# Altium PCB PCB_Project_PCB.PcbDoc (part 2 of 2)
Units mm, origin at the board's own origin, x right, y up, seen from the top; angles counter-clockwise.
Board outline 177.8 x 50.8 mm, 4 copper layers (Top Layer, Signal Layer 1, Signal Layer 2, Bottom Layer), stack 1.016 mm thick; 119 components, 90 nets, 392 pads, 439 vias.
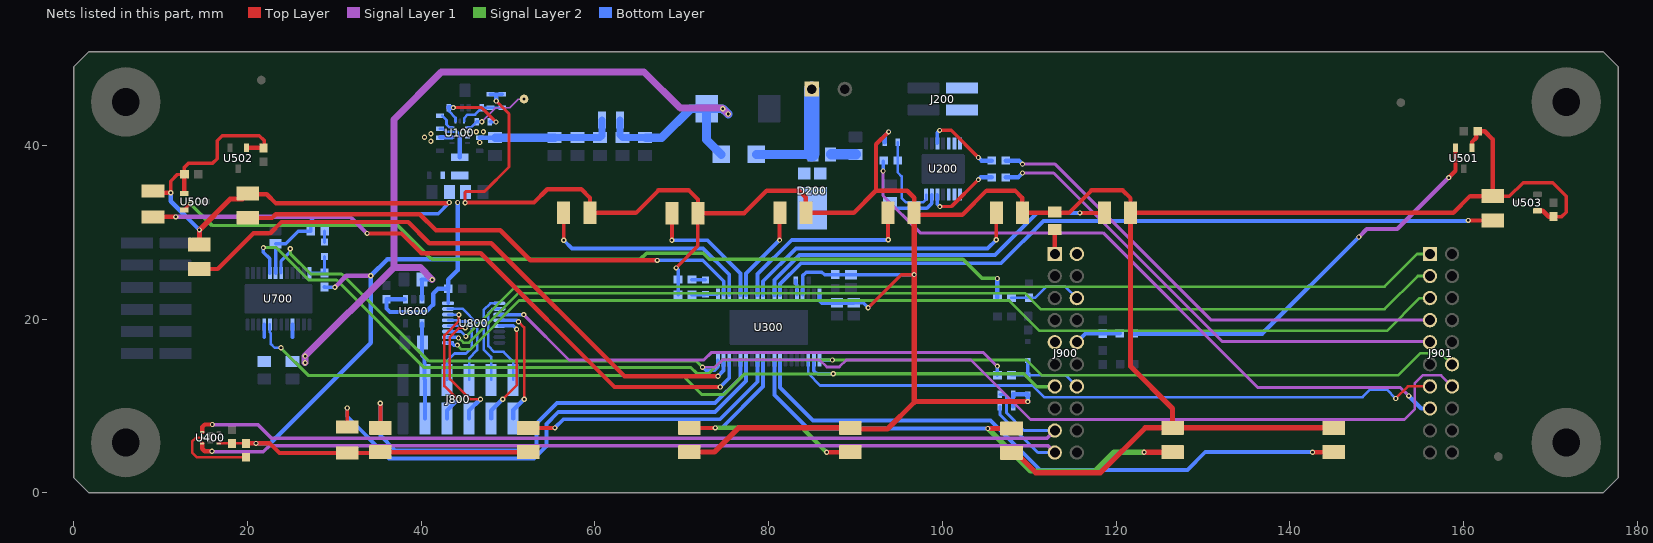
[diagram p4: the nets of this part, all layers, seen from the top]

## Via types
v1: diameter 0.6, hole 0.3, Top Layer to Bottom Layer, 386 vias
v2: diameter 0.5, hole 0.2, Top Layer to Bottom Layer, tented both sides, 30 vias
v3: diameter 0.5, hole 0.2, Top Layer to Bottom Layer, 23 vias

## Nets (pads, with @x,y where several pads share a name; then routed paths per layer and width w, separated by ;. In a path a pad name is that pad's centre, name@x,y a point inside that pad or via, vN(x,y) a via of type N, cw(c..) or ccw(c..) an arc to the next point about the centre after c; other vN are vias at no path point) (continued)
HS_DIAG: J901.9 R201.2 | length 57
  Signal Layer 1 w0.35: v1(109.22,36.83) 112.801,36.83 132.182,17.45 J901.9@156.058,17.45
  Bottom Layer w0.5: R201.2@107.277,36.322 108.712,36.322 v1(109.22,36.83)
HS_DIAG_STAT: J901.15 R203.2 | length 77.2
  Signal Layer 1 w0.35: v1(93.167,37.059) 93.167,34.214 97.434,29.947 118.491,29.947 136.322,12.116 152.73,12.116 v1(153.67,11.176)
  Bottom Layer w0.15: R203.2@93.167,38.189 R203.2@93.256,38.278
  Bottom Layer w0.152: J901.15@156.083,9.703 J901.15@156.108,9.728
  Bottom Layer w0.4: v1(93.167,37.059) R203.2@93.167,38.189
  Bottom Layer w0.5: v1(153.67,11.176) 155.118,9.728 J901.15@156.108,9.728
HS_IN: J901.7 R200.2 | length 56.4
  Signal Layer 1 w0.35: v1(109.22,37.846) 112.979,37.846 130.937,19.888 J901.7@156.108,19.888
  Bottom Layer w0.5: R200.2@107.277,38.252 108.814,38.252 v1(109.22,37.846)
INT: R300.1 U400.5 | length 9
  Top Layer w0.3: U400.5@14.798,6.35 14.072,6.35 13.64,5.918 13.64,4.648 14.199,4.089 R300.1@19.837,4.089
LATCH: J901.13 U300.3 | length 75.6
  Top Layer w0.3: v1(152.171,10.871) 153.568,12.268 J901.13@156.108,12.268
  Bottom Layer w0.3: U300.3@84.56,15.3 84.56,13.738 85.928,12.37 110.363,12.37 111.709,11.024 148.361,11.024 149.225,11.887 151.155,11.887 v1(152.171,10.871)
LMR_VCC: C114.2 R101.2 U100.5 | length 8.2
  Top Layer w0.35: v1(43.713,44.348) 46.965,44.348 v1@48.412,42.901
  Bottom Layer w0.152: R101.2@47.904,42.723 R101.2@47.93,42.697
  Bottom Layer w0.3: C114.2@43.18,44.348 43.18,43.942 43.95,43.172 U100.5@43.95,42.802
  Bottom Layer w0.4: R101.2@47.93,42.697 v1@48.387,42.697
  Bottom Layer w0.6: C114.2@43.18,44.348 v1(43.713,44.348)
  other v1: 48.616,42.697
LP_+3V3: J900.1 R903.2 | length 2.8
  Top Layer w0.5: J900.1@112.928,27.508 R903.2@112.928,30.302
LP_+5V: J900.2
MUX_A: J901.1 U800.11 | length 117.2
  Signal Layer 2 w0.3: v1(45.148,18.021) 50.876,23.749 150.876,23.749 154.635,27.508 J901.1@156.134,27.508
  Bottom Layer w0.3: U800.11@43.1,18.583 44.587,18.583 v1(45.148,18.021)
MUX_B: J901.3 U800.10 | length 117.9
  Signal Layer 2 w0.3: v1@44.298,17.856 44.856,17.297 45.517,17.297 51.206,22.987 109.474,22.987 111.303,21.158 150.901,21.158 154.711,24.968 J901.3@156.083,24.968
  Bottom Layer w0.4: U800.10@43.1,17.933 44.195,17.933 v1(44.298,17.831)
MUX_C: J901.5 U800.9 | length 118.6
  Signal Layer 2 w0.3: v1(44.171,17.018) 44.653,16.535 45.669,16.535 51.283,22.149 107.671,22.149 111.15,18.669 151.155,18.669 154.915,22.428 J901.5@156.108,22.428
  Bottom Layer w0.4: U800.9@43.1,17.283 43.474,17.283 43.749,17.008 43.759,17.018 v1(44.171,17.018)
NetC100_1: C100.1 L101.1 U100.3 U100.12@44.45,40.614 | length 5.2
  Bottom Layer w0.3: C100.1@42.164,41.91 42.526,41.91 42.859,41.577 U100.3@43.55,41.577 44.148,41.577 U100.12@44.45,41.275
  Bottom Layer w0.5: L101.1@44.45,38.642 U100.12@44.45,40.614 U100.12@44.45,41.275
NetC100_2: C100.2 U100.4 | length 2
  Bottom Layer w0.3: C100.2@42.418,43.434 42.926,42.926 42.926,42.418 43.267,42.077 U100.4@43.55,42.077
NetC101_2: C101.2 C113.1 | length 2.8
  Bottom Layer w1.2: C101.2@87.224,38.964 C113.1@90,38.964
NetC102_2: C102.2 R100.1 R102.2 U100.7 | length 5.2
  Bottom Layer w0.3: U100.7@44.95,42.802 44.95,43.121 45.364,43.536 46.203,43.536 R102.2@47.015,44.348 ; R102.2@46.99,44.348 R100.1@49.327,44.348
NetC105_1: C105.1 C106.1 C107.1 C108.1 C109.1 C110.1 L100.2 U100.2 U100.9 U100.10 | length 17.4
  Bottom Layer w0.152: C109.1@42.164,40.894 C109.1@42.197,40.927 ; C110.1@46.703,40.927 C110.1@46.736,40.894
  Bottom Layer w0.5: C109.1@42.197,40.927 U100.2@43.55,40.927
  Bottom Layer w0.55: C110.1@46.736,40.894 C108.1@48.514,40.894
  Bottom Layer w0.8: C107.1@55.372,40.894 C106.1@57.975,40.894 C105.1@60.579,40.894 60.799,41.114 L100.2@60.799,42.926
  Bottom Layer w1: C108.1@48.514,40.894 C107.1@55.372,40.894
  other v1: 46.736,40.335 41.123,40.488 40.386,40.945 41.123,41.351 46.355,41.58 47.168,41.58
NetD200_3: D200.3 U200.8 U200.9 U200.10
NetD301_1: D301.1 R301.1 | length 1.5
  Bottom Layer w0.4: R301.1@71.171,24.562 D301.1@72.694,24.562
NetD301_2: D301.2 R302.2 U300.20 | length 2.9
  Bottom Layer w0.152: R302.2@71.158,22.797 R302.2@71.171,22.809
  Bottom Layer w0.4: R302.2@71.171,22.809 D301.2@72.669,22.809 ; D301.2@72.733,22.873 U300.20@74.087,22.873
NetD700_1: D700.1 R700.1 | length 1.3
  Bottom Layer w0.152: R700.1@28.88,30.112 R700.1@28.892,30.124
  Bottom Layer w0.4: D700.1@28.88,28.867 R700.1@28.88,30.112
NetD700_2: D700.2 R701.2 U700.12 | length 3.6
  Bottom Layer w0.152: R701.2@28.871,25.302 R701.2@28.88,25.311
  Bottom Layer w0.4: U700.12@27.146,25.302 R701.2@28.871,25.302 ; R701.2@28.88,25.311 D700.2@28.88,27.217
NetD900_2: D900.2 D901.1 J900.14 R902.1 | length 9.8
  Bottom Layer w0.3: R902.1@107.95,13.554 D900.2@109.83,13.554 ; D900.2@109.804,13.538 114.198,13.538 J900.14@115.468,12.268
  Bottom Layer w0.4: D900.2@109.83,13.554 D901.1@109.83,15.24
NetJ200_1: J200.1 J200.3 U200.5 U200.6 U200.7
NetR200_1: R200.1 U200.3 | length 9
  Top Layer w0.4: v1(99.67,41.732) 101.016,41.732 v1(104.14,38.608)
  Bottom Layer w0.4: U200.3@99.426,40.237 99.426,41.489 v1(99.67,41.732)
  Bottom Layer w0.5: v1(104.14,38.608) 104.496,38.252 R200.1@105.677,38.252
NetR201_1: R201.1 U200.12 | length 8.8
  Top Layer w0.4: v1@99.72,32.969 101.041,32.969 v1(104.14,36.068)
  Bottom Layer w0.4: U200.12@99.426,34.337 99.426,33.238 v1(99.708,32.956)
  Bottom Layer w0.5: v1(104.14,36.068) 104.394,36.322 R201.1@105.677,36.322
NetR202_2: R202.2 U200.13 | length 6.4
  Bottom Layer w0.152: U200.13@98.627,34.337 U200.13@98.776,34.337
  Bottom Layer w0.4: R202.2@94.005,33.35 94.59,32.766 98.222,32.766 98.776,33.32 U200.13@98.776,34.337
NetR203_1: R203.1 R204.1 U200.14 | length 10.3
  Bottom Layer w0.3: R204.1@94.856,40.361 94.856,36.894 95.301,36.449 95.301,33.96 95.809,33.452 97.79,33.452 98.126,33.788 U200.14@98.126,34.337
NetR303_2: R303.2 U300.34 | length 1.7
  Bottom Layer w0.4: R303.2@83.109,24.46 83.109,24.079 83.26,23.928 U300.34@83.26,22.8
OUT0: D304.2 U300.8 | length 71.7
  Top Layer w0.5: v1(142.596,4.696) D304.2@145.034,4.696
  Bottom Layer w0.45: U300.8@81.31,15.3 81.31,12.162 85.115,8.357 105.537,8.357 111.252,2.642 128.194,2.642 130.251,4.699 140.995,4.699 140.998,4.696 v1(142.596,4.696)
OUT1: D317.2 D319.2 U300.9 | length 57.1
  Top Layer w0.6: v1(105.232,7.417) D319.2@107.947,7.417 ; v1(123.212,4.696) D317.2@126.492,4.696
  Signal Layer 2 w0.6: v1(105.232,7.417) 110.134,2.515 117.571,2.515 119.752,4.696 v1(123.212,4.696)
  Bottom Layer w0.45: U300.9@80.66,15.3 80.66,11.263 84.506,7.417 v1(105.232,7.417)
OUT2: D316.2 D318.2 U300.11 | length 30.2
  Top Layer w0.45: D318.2@70.866,7.496 v1@73.86,7.496
  Top Layer w0.5: v1(86.668,4.696) D316.2@89.408,4.696
  Signal Layer 2 w0.5: v1(73.863,7.493) 83.871,7.493 v1(86.668,4.696)
  Bottom Layer w0.45: v1(73.863,7.493) 74.6,7.493 79.36,12.253 U300.11@79.36,15.3
OUT3: D310.2 U300.12 | length 31.1
  Top Layer w0.45: D310.2@52.324,7.496 v1@55.394,7.496
  Bottom Layer w0.45: v1(55.397,7.493) 55.397,7.518 56.363,8.484 74.397,8.484 78.71,12.797 U300.12@78.71,15.3
OUT4: D312.2 U300.14 | length 58.7
  Top Layer w0.45: D312.2@31.496,7.596 v1(31.496,9.779)
  Bottom Layer w0.45: v1(31.496,9.779) 31.496,8.788 36.297,3.988 53.01,3.988 54.432,5.41 54.432,7.95 55.778,9.296 73.812,9.296 77.41,12.894 U300.14@77.41,15.3
OUT5: D306.2 U300.15 | length 55.6
  Top Layer w0.45: D306.2@35.306,7.496 v1(35.306,10.338)
  Bottom Layer w0.45: v1(35.306,10.338) 35.306,6.604 36.995,4.915 52.616,4.915 53.264,5.563 53.264,7.976 55.626,10.338 73.838,10.338 76.76,13.26 U300.15@76.76,15.3
OUT6: D314.2 U300.17 | length 76.9
  Top Layer w0.152: v1(11.759,31.774) v1@11.76,31.775
  Top Layer w0.5: D314.2@9.144,31.774 v1(11.759,31.774) ; v1(33.782,29.87) 37.744,29.87 40.03,27.584 46.863,27.584 62.255,12.192 v1(74.422,12.192)
  Signal Layer 1 w0.5: v1(11.759,31.774) 31.878,31.774 v1(33.782,29.87)
  Bottom Layer w0.45: v1(74.422,12.192) 75.46,13.23 U300.17@75.46,15.3
OUT7: D308.2 U300.18 | length 71.4
  Top Layer w0.5: D308.2@14.478,25.778 16.583,25.778 20.701,29.896 22.631,29.896 23.927,31.191 38.506,31.191 40.945,28.753 48.082,28.753 63.398,13.437 v1(74.168,13.437)
  Bottom Layer w0.45: v1@74.193,13.462 74.81,14.079 U300.18@74.81,15.3
OUT8: D305.2 U300.22 | length 26.2
  Top Layer w0.152: D305.2@56.412,32.233 D305.2@56.413,32.231
  Top Layer w0.45: v1(56.413,29.083) D305.2@56.413,32.231
  Bottom Layer w0.45: v1(56.413,29.083) 57.353,28.143 72.441,28.143 75.46,25.124 U300.22@75.46,22.8
OUT9: D302.2 U300.21 | length 59.6
  Top Layer w0.5: D302.2@20.117,31.648 22.835,31.648 23.266,32.08 39.853,32.08 41.707,30.226 49.098,30.226 52.553,26.772 v1(67.183,26.772)
  Bottom Layer w0.4: v1(67.183,26.772) 72.415,26.772 74.81,24.377 U300.21@74.81,22.8
OUT10: D309.2 U300.25 | length 11
  Top Layer w0.152: D309.2@81.255,32.209 D309.2@81.279,32.233
  Top Layer w0.45: v1(81.255,29.108) D309.2@81.255,32.209
  Bottom Layer w0.45: U300.25@77.41,22.8 77.41,25.264 v1(81.255,29.108)
OUT11: D303.2 U300.24 | length 15.1
  Top Layer w0.152: D303.2@68.858,32.207 D303.2@68.859,32.206
  Top Layer w0.45: v1(68.859,29.083) D303.2@68.859,32.206
  Bottom Layer w0.45: v1(68.859,29.083) 72.949,29.083 76.76,25.272 U300.24@76.76,22.8
OUT12: D313.2 U300.28 | length 33.5
  Top Layer w0.152: D313.2@106.196,32.233 D313.2@106.197,32.231
  Top Layer w0.45: v1(106.197,29.134) D313.2@106.197,32.231
  Bottom Layer w0.45: U300.28@79.36,22.8 79.36,24.369 83.134,28.143 105.207,28.143 v1(106.197,29.134)
OUT13: D307.2 U300.27 | length 22.2
  Top Layer w0.152: D307.2@93.75,32.233 D307.2@93.751,32.231
  Top Layer w0.45: v1(93.751,29.134) D307.2@93.751,32.231
  Bottom Layer w0.45: U300.27@78.71,22.8 78.71,25.192 82.652,29.134 v1(93.751,29.134)
OUT14: D315.2 U300.31 | length 86.3
  Top Layer w0.152: v1(160.528,31.369) v1@160.531,31.366
  Top Layer w0.45: v1@160.531,31.366 D315.2@163.322,31.366
  Bottom Layer w0.45: U300.31@81.31,22.8 81.31,24.033 83.718,26.441 106.756,26.441 111.633,31.318 160.477,31.318 v1(160.528,31.369)
OUT15: D311.2 U300.30 | length 42.9
  Top Layer w0.45: v1(115.824,32.233) D311.2@118.642,32.233
  Bottom Layer w0.152: 80.657,24.498 80.66,24.494 ; U300.30@80.66,22.8 U300.30@80.67,22.81
  Bottom Layer w0.45: 80.657,24.498 83.541,27.381 106.045,27.381 110.896,32.233 v1(115.824,32.233) ; U300.30@80.66,22.8 80.66,24.494
PG: R101.1 TP100.1 U100.8 | length 7.8
  Signal Layer 1 w0.15: v1(46.99,42.723) 48.616,44.348 50.216,44.348 51.207,45.339 v1(51.841,45.339)
  Bottom Layer w0.3: U100.8@45.35,42.077 45.735,42.077 R101.1@46.38,42.723
  Bottom Layer w0.4: R101.1@46.38,42.723 v1(46.99,42.723)
RESET: J900.9
SCK: J900.13 U300.2 U700.20 | length 100.2
  Signal Layer 2 w0.152: J900.13@112.878,12.217 J900.13@112.928,12.268
  Signal Layer 2 w0.35: v1(23.876,16.713) 23.876,16.662 27,13.538 70.079,13.538 72.263,11.354 74.879,11.354 77.241,13.716 v1(87.427,13.716)
  Signal Layer 2 w0.4: v1(87.427,13.716) 109.372,13.716 110.871,12.217 J900.13@112.878,12.217
  Bottom Layer w0.3: U700.20@22.596,19.402 22.596,18.476 22.708,18.364 22.708,17.145 23.139,16.713 v1(23.876,16.713)
  Bottom Layer w0.4: U300.2@85.21,15.3 85.21,14.079 85.573,13.716 v1(87.427,13.716)
SCL: J900.17 R901.1 U400.4 | length 109
  Top Layer w0.5: U400.4@14.798,7 14.798,7.584 15.088,7.874 v1(15.977,7.874)
  Signal Layer 1 w0.4: v1(15.977,7.874) 21.209,7.874 22.758,6.325 112.065,6.325 J900.17@112.928,7.188
  Bottom Layer w0.35: R901.1@106.604,11.354 107.112,11.354 107.366,11.1 107.366,9.22 109.398,7.188 J900.17@112.928,7.188
SDA: J900.19 R900.1 U400.6 | length 108.6
  Top Layer w0.5: U400.6@14.798,5.7 14.798,5.09 15.088,4.801 v1(15.926,4.801)
  Signal Layer 1 w0.152: v1(15.926,4.801) v1@15.977,4.75
  Signal Layer 1 w0.4: v1@15.977,4.75 21.844,4.75 22.555,5.461 112.116,5.461 J900.19@112.928,4.648
  Bottom Layer w0.152: R900.1@106.604,9.957 R900.1@106.629,9.931
  Bottom Layer w0.35: R900.1@106.629,9.931 106.629,8.992 110.973,4.648 J900.19@112.928,4.648
SDI: J901.12 U300.1 U700.5 | length 150.5
  Signal Layer 2 w0.3: v1(87.334,15.3) 109.693,15.3 111.455,13.538 152.451,13.538 154.991,16.078 157.378,16.078 J901.12@158.674,14.783
  Signal Layer 2 w0.35: v1(21.844,28.245) 23.317,28.245 27.051,24.511 30.277,24.511 40.361,14.427 71.06,14.427 71.72,13.767 73.127,13.767 74.676,15.316 v1@87.351,15.316
  Bottom Layer w0.4: v1(21.844,28.245) 21.844,27.722 22.546,27.02 22.546,27.009 22.596,26.959 U700.5@22.596,25.302 ; U300.1@85.86,15.3 v1(87.334,15.3)
SDO: J901.14 U300.19 U700.7 | length 154
  Signal Layer 1 w0.152: 88.138,14.503 88.163,14.529
  Signal Layer 1 w0.3: v1(72.39,14.478) 73.838,14.478 74.676,15.316 85.877,15.316 86.69,14.503 88.138,14.503 ; 88.163,14.529 88.935,15.3 103.293,15.3 110.134,8.458 153.162,8.458 154.381,9.677 154.381,12.649 155.27,13.538 157.378,13.538 J901.14@158.648,12.268
  Signal Layer 2 w0.35: v1(24.943,28.118) 24.943,27.534 27.28,25.197 30.861,25.197 40.894,15.164 71.704,15.164 v1(72.39,14.478)
  Bottom Layer w0.35: U700.7@23.896,25.302 23.896,26.716 24.943,27.762 v1(24.943,28.118)
  Bottom Layer w0.4: v1(72.39,14.478) 72.746,14.122 73.787,14.122 74.16,14.495 U300.19@74.16,15.3
SIN1: R906.2 U500.2 | length 100.2
  Top Layer w0.4: U500.2@12.745,32.578 v1(13.443,33.278)
  Signal Layer 2 w0.4: v1(13.443,33.278) 15.936,30.785 37.328,30.785 41.128,26.984 41.215,26.984 41.275,26.924 65.253,26.924 65.938,27.61 72.466,27.61 73.177,26.899 102.362,26.899 104.572,24.689 v1(106.324,24.689)
  Bottom Layer w0.152: R906.2@106.324,22.492 R906.2@106.337,22.479
  Bottom Layer w0.5: R906.2@106.324,22.492 v1(106.324,24.689)
SIN1_flt: C900.1 J900.6 R906.1 | length 8.6
  Bottom Layer w0.152: R906.1@107.937,22.479 R906.1@107.95,22.466
  Bottom Layer w0.3: R906.1@107.95,22.466 C900.1@109.957,22.466 110.655,22.466 111.912,23.724 114.173,23.724 J900.6@115.468,22.428
SIN2: R908.2 U501.2 | length 47.4
  Top Layer w0.5: v1@158.267,36.297 159.05,37.079 U501.2@159.05,39.732
  Signal Layer 1 w0.5: v1(147.928,29.464) 148.843,30.378 152.348,30.378 v1(158.266,36.297)
  Bottom Layer w0.5: R908.2@122.022,18.339 136.804,18.339 v1@147.93,29.464
SIN2_flt: C902.1 J900.10 R908.1 | length 5.4
  Bottom Layer w0.152: C902.1@118.44,18.352 C902.1@118.453,18.364
  Bottom Layer w0.5: J900.10@115.468,17.348 116.472,18.352 C902.1@118.44,18.352 ; C902.1@118.453,18.364 R908.1@120.409,18.364
Tsense1: J800.5 U800.13 | length 11.2
  Bottom Layer w0.152: U800.13@43.1,19.883 U800.13@43.105,19.888
  Bottom Layer w0.3: J800.5@42.977,13.018 42.977,15.189 43.84,16.053 45.161,16.053 45.847,16.739 45.847,19.177 45.735,19.289 45.735,19.294 45.354,19.675 45.349,19.675 45.288,19.736 44.217,19.736 44.064,19.888 U800.13@43.105,19.888
Tsense2: J800.6 U800.14 | length 15.1
  Top Layer w0.3: v1(44.247,10.795) 44.171,10.795 42.672,12.294 42.672,18.136 44.348,19.812 v1(44.348,20.523)
  Bottom Layer w0.152: v1@44.339,20.533 v1(44.348,20.523)
  Bottom Layer w0.3: U800.14@43.1,20.533 v1@44.339,20.533
  Bottom Layer w0.5: J800.6@42.977,8.572 42.977,9.5 44.247,10.77 v1(44.247,10.795)
Tsense3: J800.7 U800.15 | length 11
  Bottom Layer w0.3: U800.15@43.053,21.184 44.806,21.184 46.457,19.533 46.457,16.434 45.517,15.494 J800.7@45.517,13.018
Tsense4: J800.8 U800.12 | length 16.4
  Top Layer w0.3: v1(45.085,19.025) 44.399,19.025 43.307,17.933 43.307,13.106 45.618,10.795 v1(46.838,10.795)
  Bottom Layer w0.3: U800.12@43.1,19.233 44.877,19.233 v1(45.085,19.025)
  Bottom Layer w0.5: J800.8@45.517,8.572 45.517,9.5 46.812,10.795 v1(46.838,10.795)
Tsense5: J800.9 U800.1 | length 10.5
  Bottom Layer w0.3: J800.9@48.057,13.018 48.057,15.646 47.193,16.51 47.193,21.057 47.97,21.833 U800.1@49,21.833
Tsense6: J800.10 U800.5 | length 13.6
  Top Layer w0.3: v1(49.403,10.795) 50.99,12.383 v1(50.99,18.834)
  Bottom Layer w0.4: U800.5@49,19.233 50.592,19.233 v1(50.99,18.834)
  Bottom Layer w0.5: J800.10@48.057,8.572 48.057,9.474 49.378,10.795 v1(49.403,10.795)
Tsense7: J800.11 U800.2 | length 11
  Bottom Layer w0.3: U800.2@49,21.183 48.209,21.183 47.727,20.701 47.727,16.891 48.387,16.231 49.505,16.231 50.597,15.138 J800.11@50.597,13.018
Tsense8: J800.12 U800.4 | length 14.2
  Top Layer w0.3: v1(51.206,19.71) 51.867,19.05 v1(51.867,10.795)
  Bottom Layer w0.4: U800.4@49,19.883 51.034,19.883 v1(51.206,19.71)
  Bottom Layer w0.5: J800.12@50.597,8.572 50.597,9.55 51.841,10.795 v1(51.867,10.795)
TsenseOut: R902.2 U800.3 | length 61.6
  Signal Layer 1 w0.35: v1(51.8,20.533) 51.8,20.513 57.014,15.3 72.526,15.3 73.381,16.154 104.724,16.154 106.324,14.554 v1(106.324,14.605)
  Bottom Layer w0.152: R902.2@106.324,13.559 R902.2@106.337,13.546
  Bottom Layer w0.4: U800.3@49,20.533 v1(51.8,20.533) ; R902.2@106.324,13.559 v1(106.324,14.605)
V_bat: C101.1 D100.2 D200.1 D200.2 J100.1 | length 13.8
  Bottom Layer w1: D100.2@78.556,38.964 C101.1@84.887,38.964
  Bottom Layer w1.8: C101.1@84.963,39.04 J100.1@84.963,46.482
V_supply: C103.1 C104.1 C600.1 C700.1 C702.1 D100.1 D101.1 L100.1 U600.3 U700.16 U700.21 | length 108.3
  Signal Layer 1 w0.5: v1@74.701,44.196 v1(74.727,44.221)
  Signal Layer 1 w0.8: v1(26.645,14.986) v1(26.645,15.748) 36.855,25.959 36.855,43.002 42.316,48.463 65.659,48.463 69.825,44.298 74.651,44.298 v1(75.336,43.612) ; 36.805,25.933 39.903,25.933 v1(41.275,24.562)
  Bottom Layer w0.152: C600.1@40.081,24.562 C600.1@40.091,24.552
  Bottom Layer w0.45: 21.946,17.958 U700.21@21.946,19.402 ; 25.196,17.933 U700.16@25.196,19.402
  Bottom Layer w0.5: C600.1@40.081,24.562 v1(41.275,24.562) ; U600.3@40.091,22.279 C600.1@40.091,24.552
  Bottom Layer w0.8: L100.1@62.899,42.926 62.899,41.177 C104.1@63.182,40.894 C103.1@65.786,40.894
  Bottom Layer w1: C103.1@65.862,40.869 67.666,40.869 71.018,44.221 D101.1@72.854,44.221 ; D100.1@74.556,38.957 72.854,40.659 D101.1@72.854,44.221 ; v1(75.336,43.612) v1(74.727,44.221) D101.1@72.854,44.221
V_track: C601.1 J800.3 J800.4 U600.4 | length 11.1
  Bottom Layer w0.152: J800.3@40.386,13.068 J800.3@40.437,13.018
  Bottom Layer w0.5: U600.4@40.107,19.507 40.107,15.85 40.386,15.57 J800.3@40.386,13.068 ; J800.4@40.437,8.572 J800.3@40.437,13.018
VCC_3V3: C102.1 C111.1 C112.1 C115.1 C300.1 C301.1 C302.1 C303.1 C304.1 C500.1 C501.1 C502.1 C503.1 C602.1 C701.1 C800.1 D302.1 D303.1 D304.1 D305.1 D306.1 D307.1 D308.1 D309.1 D310.1 D311.1 D312.1 D313.1 D314.1 D315.1 D316.1 D317.1 D318.1 D319.1 D900.1 L101.2 R100.2 R204.2 R300.2 R301.2 R302.1 R700.2 R701.1 R900.2 R901.2 R903.1 U300.35 U300.38 U400.1 U500.1 U501.1 U502.1 U503.1 U600.1 U700.6 U800.16 | length 554.2
  Top Layer w0.15: v1@93.777,41.554 v1(93.802,41.554) ; D304.1@145.034,7.496 D304.1@145.037,7.493
  Top Layer w0.152: v1(11.175,34.544) v1@11.175,34.545 ; C500.1@12.738,36.652 12.745,36.659 C500.1@12.764,36.678 ; R300.2@19.835,5.7 R300.2@19.837,5.702 ; U502.1@19.898,39.732 U502.1@19.917,39.713 ; v1@43.129,33.325 v1(43.231,33.426) ; v1(96.737,25.134) v1@96.75,25.134 ; 96.75,10.541 96.775,10.516 ; C501.1@161.442,41.466 C501.1@161.607,41.631 ; D315.1@163.322,34.166 163.319,34.163 D315.1@163.344,34.138 ; C503.1@170.32,31.801 C503.1@170.332,31.814
  Top Layer w0.3: U400.1@16.698,5.7 C300.1@18.237,5.7 R300.2@19.835,5.7
  Top Layer w0.35: v1(45.06,33.401) 45.06,34.62 45.161,34.722 47.32,34.722 50.114,37.516 50.114,43.637 v1(48.641,45.11)
  Top Layer w0.4: v1@11.176,34.544 11.176,35.89 11.938,36.652 C500.1@12.738,36.652 ; C500.1@12.764,36.678 12.764,37.478 13.259,37.973 16.027,37.973 16.535,38.481 16.535,40.538 17.12,41.123 21.387,41.123 21.92,40.589 C502.1@21.92,39.776 ; v1(69.342,25.908) 71.858,28.424 D303.1@71.858,32.207 ; v1(91.44,21.311) 95.263,25.134 v1(96.737,25.134) ; D315.1@163.344,34.138 165.252,34.138 166.827,35.712 170.231,35.712 171.78,34.163 171.78,32.309 171.285,31.814 C503.1@170.332,31.814
  Top Layer w0.5: D314.1@9.144,34.774 9.473,34.774 9.703,34.544 v1@11.176,34.544 ; U500.1@12.745,34.478 C500.1@12.745,36.659 ; R300.2@19.837,5.702 v1(20.993,5.702) 22.593,5.702 23.7,4.596 D312.1@31.496,4.596 35.206,4.596 D306.1@35.306,4.696 D310.1@52.324,4.696 ; U502.1@19.917,39.713 C502.1@21.869,39.713 ; D302.1@20.091,34.392 22.225,34.392 23.292,33.325 v1@43.129,33.325 ; v1@45.11,33.426 52.984,33.426 54.508,34.95 58.445,34.95 59.436,33.96 D305.1@59.436,32.233 ; D305.1@59.412,32.233 D305.1@59.436,32.233 ; 92.481,34.773 92.354,34.9 92.354,40.132 v1@93.777,41.554 ; 96.75,10.441 96.75,10.541 ; U501.1@160.95,39.732 160.95,40.402 161.442,40.894 C501.1@161.442,41.466 ; C501.1@161.646,41.631 162.408,41.631 163.322,40.716 D315.1@163.322,34.166 ; D315.1@163.319,34.163 160.731,34.163 158.801,32.233 D311.1@121.642,32.233 121.642,33.934 120.753,34.823 117.145,34.823 114.554,32.233 D313.1@109.196,32.233 109.196,33.96 108.358,34.798 105.08,34.798 102.286,32.004 96.979,32.004 D307.1@96.75,32.233 96.75,33.984 95.961,34.773 92.329,34.773 89.789,32.233 D309.1@84.279,32.233 84.279,34.009 83.49,34.798 79.781,34.798 77.191,32.207 D303.1@71.858,32.207 71.858,33.781 70.815,34.823 67.31,34.823 64.719,32.233 D305.1@59.436,32.233 ; U503.1@168.484,32.476 169.098,32.476 169.774,31.801 C503.1@170.32,31.801
  Top Layer w0.6: D308.1@14.478,28.578 14.478,30.277 18.034,33.833 19.406,33.833 D302.1@20.041,34.468 ; D318.1@70.739,4.724 73.762,4.724 76.533,7.496 D316.1@89.408,7.496 ; D316.1@89.383,7.366 93.675,7.366 96.75,10.441 ; 96.75,10.541 96.75,25.134 D307.1@96.75,32.233 ; 96.775,10.516 v1(109.83,10.516) ; D319.1@107.874,4.648 108.433,4.648 110.744,2.337 118.186,2.337 123.345,7.496 D317.1@126.492,7.496 ; D311.1@121.642,32.233 121.642,14.578 126.492,9.728 D317.1@126.492,7.496 ; D304.1@145.034,7.496 D317.1@126.492,7.496
  Signal Layer 1 w0.5: v1(30.074,23.673) 31.394,24.994 v1(34.214,24.994)
  Bottom Layer w0.152: C701.1@23.241,28.231 C701.1@23.246,28.226 ; U600.1@38.124,22.289 38.163,22.25 U600.1@38.191,22.279 ; C800.1@43.1,23.479 43.104,23.482 C800.1@43.104,23.495 ; 48.641,45.86 48.654,45.872 ; C302.1@87.617,25.095 C302.1@87.655,25.133
  Bottom Layer w0.4: C701.1@23.241,28.689 24.421,28.689 25.857,30.124 R700.2@27.292,30.124 ; U700.6@23.246,25.302 C701.1@23.246,28.226 ; R700.2@27.28,30.15 27.28,31.318 28.118,32.156 41.961,32.156 v1(43.231,33.426) ; U800.16@43.1,21.833 C800.1@43.1,23.479 ; C102.1@47.981,45.872 48.654,45.872 R100.2@49.327,45.872 ; v1(69.342,25.908) 69.571,25.679 R301.2@69.571,24.562 R302.1@69.571,22.809 ; U300.35@83.91,22.8 83.91,25.033 84.303,25.425 86.131,25.425 86.462,25.095 C302.1@87.617,25.095 ; C302.1@87.655,25.133 C301.1@89.484,25.134 ; C301.1@89.484,25.134 v1(96.737,25.134) ; C304.1@89.797,21.883 90.868,21.883 v1(91.44,21.311)
  Bottom Layer w0.45: R701.1@28.88,23.711 28.918,23.673 v1(30.074,23.673) ; U300.38@85.86,22.8 85.86,22.141 86.118,21.883 C303.1@87.867,21.883 C304.1@89.797,21.883
  Bottom Layer w0.5: v1(11.175,34.544) 11.175,33.579 v1(14.477,30.277) ; v1(20.993,5.702) 22.644,5.702 34.214,17.272 v1(34.214,24.994) 36.119,26.899 44.196,26.899 ; C602.1@36.017,22.289 U600.1@38.124,22.289 ; C602.1@36.017,22.301 36.017,21.234 36.424,20.828 40.526,20.828 41.377,21.679 41.377,22.936 41.935,23.495 43.104,23.495 43.104,24.536 44.196,25.629 44.196,26.899 ; v1(44.196,33.426) 44.196,26.899 ; v1(48.641,45.11) 48.641,45.86 ; R204.2@93.345,40.361 93.345,41.097 v1(93.802,41.554) ; R900.2@108.128,9.957 R901.2@108.128,11.354 D900.1@109.83,11.354 v1(109.83,10.516)
pads on no net: FID1.1 FID2.1 FID3.1 H1.1 H2.1 H3.1 H4.1 J900.3 J900.5 J900.7 J900.11 J900.15 J900.16 J900.18 J900.20 J901.6 J901.8 J901.10 J901.16 J901.17 J901.19 LBL1.0 U100.12@44.45,40.107 U100.12@44.45,41.122 U200.1 U200.4 U200.11 U200.15@100.076,37.287 U300. U300.7 U300.10 U300.13 U300.16 U300.23 U300.26 U300.29 U300.32 U700.25@23.571,22.352

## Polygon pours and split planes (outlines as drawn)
V_bat on Bottom Layer "Bottom Layer-No Net 7" (solid, pour order 25): 86.614,35.814 86.868,36.068 86.868,37.338 86.614,37.592 86.106,37.592 85.852,37.846 85.852,39.624 85.598,39.878 84.328,39.878 84.074,39.624 84.074,37.846 83.82,37.592 83.312,37.592 83.058,37.338 83.058,36.068 83.312,35.814
V_supply on Bottom Layer "Bottom Layer-No Net 3" (solid, pour order 17): 21.742,20.193 22.123,20.193 22.25,20.066 22.25,16.866 22.86,16.256 24.13,16.256 24.867,16.993 24.867,20.041 25.019,20.193 25.349,20.193 25.476,20.066 25.476,17.196 26.416,16.256 26.67,16.256 27.178,15.748 27.178,14.986 26.67,14.478 21.082,14.478 20.828,14.732 20.828,16.256 21.641,17.069 21.641,20.091
NetC105_1 on Bottom Layer "Bottom Layer-No Net 1" (solid, pour order 13): 43.942,41.046 43.79,41.199 41.758,41.199 41.224,41.732 40.538,41.732 39.98,41.173 39.98,40.691 40.538,40.132 41.275,40.132 41.783,40.64 43.79,40.64 43.942,40.792
AGND on Bottom Layer "Bottom Layer-No Net 2" (solid, remove dead copper, pour order 9): 44.78,45.974 44.323,45.517 44.323,43.942 44.391,43.874 45.679,43.874 45.771,43.966 45.771,45.517 45.314,45.974
VCC_3V3 on Bottom Layer "Bottom Layer-No Net" (solid, remove dead copper, pour order 5): 45.72,36.83 45.466,37.084 42.691,37.084 42.418,36.811 42.418,33.528 42.926,33.02 45.212,33.02 45.72,33.528
NetC105_1 on Bottom Layer "BOTTOM_LAYER_NETC105_1_P002" (solid, pour order 2): 45.822,41.732 46.076,41.986 47.574,41.986 47.892,41.669 48.92,41.669 49.327,41.669 49.327,40.347 48.96,39.98 46.584,39.98 45.796,40.767 45.034,40.767 44.958,40.843 44.958,41.732
NetJ200_1 on Bottom Layer "Bottom Layer-No Net 4" (solid, pour order 19): 101.854,39.116 104.394,41.656 104.394,47.498 104.14,47.752 100.584,47.752 100.33,47.498 100.33,39.37 100.584,39.116
GND on Bottom Layer "Bottom Layer-No Net 5" (solid, pour order 21): 95.758,33.782 95.758,47.498 96.012,47.752 99.568,47.752 99.822,47.498 99.822,42.418 99.06,41.656 99.06,33.528 96.012,33.528
NetD200_3 on Bottom Layer "Bottom Layer-No Net 6" (solid, pour order 23): 102.108,35.56 102.362,35.306 102.362,30.48 101.854,29.972 83.312,29.972 82.804,30.48 82.804,35.052 83.058,35.306 100.33,35.306 100.584,35.56
GND on Bottom Layer "Bottom Layer-No Net 8" (solid, pour order 27): -0.025,50.8 177.775,50.8 177.775,0 -0.025,0
VCC_3V3 on Top Layer "Bottom Layer-No Net" (solid, remove dead copper, pour order 15): 45.72,35.027 45.415,35.331 42.697,35.331 42.418,35.052 42.418,33.528 42.926,33.02 45.212,33.02 45.72,33.528
NetC105_1 on Top Layer "Top Layer-No Net" (solid, remove dead copper, pour order 11): 47.549,41.783 47.346,41.986 40.64,41.986 39.98,41.326 39.98,40.64 40.64,39.98 46.99,39.98 47.549,40.538
GND on Top Layer "Bottom Layer-No Net 8" (solid, pour order 29): 0,50.8 177.8,50.8 177.8,0 0,0

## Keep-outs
Keep-Out Layer:
  text ".Layer_Name" at 48.438,81.788 h1.52

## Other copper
Top Layer:
  pour cut-out: 51.308,43.18 53.34,45.212 66.548,45.212 68.834,42.926 68.834,37.592 67.056,35.814 53.086,35.814 51.308,37.592
  text ".Layer_Name" at 8.814,78.334 h1.52
Bottom Layer:
  pour cut-out: 51.308,43.18 53.34,45.212 66.548,45.212 68.834,42.926 68.834,37.592 67.056,35.814 53.086,35.814 51.308,37.592
  text ".Layer_Name" at 45.314,82.804 h1.52

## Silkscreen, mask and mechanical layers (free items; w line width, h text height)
Top Overlay:
  region: 31.445,46.482 23.825,46.482 23.825,43.942 31.445,43.942
  lines w0.254: 15.579,37.226 cw(c18.948,33.532) 16.902,38.094 ; 162.037,38.098 cw(c160,33.532) 164.679,35.295
  text ".Layer_Name" at 8.814,81.966 h1.52
  text "'.PRJ_Number'.PCB_Rev-" at 121.971,37.643 h2.75
Bottom Overlay:
  lines w0.102: 114.198,26.187 cw(c114.198,26.238) 114.198,26.289 ; 114.198,26.187 ccw(c114.198,26.238) 114.198,26.289 ; 114.198,26.187 cw(c114.198,26.238) 114.198,26.289 ; 114.198,26.187 ccw(c114.198,26.238) 114.198,26.289 ; 116.738,2.946 cw(c116.738,2.997) 116.738,3.048 ; 116.738,2.946 ccw(c116.738,2.997) 116.738,3.048 ; 116.738,2.946 cw(c116.738,2.997) 116.738,3.048 ; 116.738,2.946 ccw(c116.738,2.997) 116.738,3.048 ; 116.738,29.108 cw(c116.738,29.159) 116.738,29.21 ; 116.738,29.108 ccw(c116.738,29.159) 116.738,29.21 ; 116.738,29.108 cw(c116.738,29.159) 116.738,29.21 ; 116.738,29.108 ccw(c116.738,29.159) 116.738,29.21 ; 159.918,2.946 cw(c159.918,2.997) 159.918,3.048 ; 159.918,2.946 ccw(c159.918,2.997) 159.918,3.048 ; 159.918,2.946 cw(c159.918,2.997) 159.918,3.048 ; 159.918,2.946 ccw(c159.918,2.997) 159.918,3.048 ; 111.735,2.997 cw(c111.735,3.048) 111.735,3.099 cw(c111.735,3.048) 111.735,2.997 ; 111.735,29.058 cw(c111.735,29.108) 111.735,29.159 cw(c111.735,29.108) 111.735,29.058 ; 111.76,2.946 cw(c111.76,2.997) 111.76,3.048 cw(c111.76,2.997) 111.76,2.946 ; 111.785,26.187 cw(c111.785,26.238) 111.785,26.289 cw(c111.785,26.238) 111.785,26.187 ; 111.785,29.108 cw(c111.785,29.159) 111.785,29.21 cw(c111.785,29.159) 111.785,29.108 ; 114.198,29.108 cw(c114.198,29.159) 114.198,29.21 cw(c114.198,29.159) 114.198,29.108 ; 154.915,2.997 cw(c154.915,3.048) 154.915,3.099 cw(c154.915,3.048) 154.915,2.997 ; 154.915,29.058 cw(c154.915,29.108) 154.915,29.159 cw(c154.915,29.108) 154.915,29.058 ; 154.94,2.946 cw(c154.94,2.997) 154.94,3.048 cw(c154.94,2.997) 154.94,2.946 ; 154.965,26.187 cw(c154.965,26.238) 154.965,26.289 cw(c154.965,26.238) 154.965,26.187 ; 154.965,29.108 cw(c154.965,29.159) 154.965,29.21 cw(c154.965,29.159) 154.965,29.108
  lines w0.203: 111.735,3.048 111.735,29.108 ; 111.76,2.997 116.738,2.997 116.738,29.159 111.785,29.159 ; 111.785,26.238 114.198,26.238 114.198,29.159 ; 154.915,3.048 154.915,29.108 ; 154.94,2.997 159.918,2.997 159.918,29.159 154.965,29.159 ; 154.965,26.238 157.378,26.238 157.378,29.159
  text ".Layer_Name" at 45.314,75.37 h1.52
Top Paste:
  text ".Layer_Name" at 8.814,67.437 h1.52
Bottom Paste:
  text ".Layer_Name" at 45.314,60.503 h1.52
Top Solder:
  text ".Layer_Name" at 8.814,74.701 h1.52
  text ".Layer_Name" at 8.814,71.069 h1.52
Bottom Solder:
  text ".Layer_Name" at 45.314,79.087 h1.52
Drill Guide:
  text ".Layer_Name" at 48.438,78.417 h1.52
M1 Board Outline:
  the board outline again, w0.254
  text ".Layer_Name" at 48.438,75.046 h1.52
M2 Board Dimensions:
  rectangle: 3.175,-10.16 12.7,-6.985
  rectangle: 0,-6.985 3.175,-3.81
  lines w0.178: 0,-6.985 25.4,-6.985 ; 3.175,-10.16 3.175,-3.81 ; 6.35,-10.16 6.35,-3.81 ; 12.7,-10.16 12.7,-3.81 ; 19.05,-10.16 19.05,-3.81 ; 0,-10.16 0,-3.81 25.4,-3.81 25.4,-10.16 0,-10.16
  text ".Layer_Name" at 14.656,-21.806 h1.52
M3 3D STEP Top:
  text ".Layer_Name" at 8.814,63.805 h1.52
M4 3D STEP Bottom:
  text ".Layer_Name" at 45.314,71.653 h1.52
M5 Assembly Top:
  lines w0.254: -7.417,-23.626 160.223,-23.626 ; -7.417,-18.462 160.274,-18.462 ; -7.417,-13.297 -7.417,-28.791 94.31,-28.791 160.274,-28.791 160.274,-13.297 -7.404,-13.297 -7.404,-28.791 32.614,-28.791 ; 55.194,-28.791 55.194,-13.297 ; 87.376,-18.462 87.376,-13.297 ; 108.712,-18.462 108.712,-13.297 ; 124.511,-28.956 124.511,-23.804
  text "COMPONENTS MARKED 'DNP' SHOULD NOT BE POPULATED." at 29.299,-8.09 h1.52
  text "ASSEMBLY VARIANT:" at 29.286,-11.024 h1.52
  text ".VariantName" at 55.601,-11.024 h1.52
  text "PCB VIEWED FROM TOP SIDE" at -5.804,-16.654 h1.52
  text "BOARD #:" at 57.099,-16.654 h1.52
  text ".PRJ_Number" at 70.955,-16.654 h1.52
  text "REV:" at 92.405,-16.654 h1.52
  text ".PCB_Rev" at 99.809,-16.654 h1.52
  text "SVN REV:" at 113.69,-16.654 h1.52
  text ".VersionControl_RevNumber" at 126.543,-16.654 h1.52
  text "TID #:" at 57.099,-21.819 h1.52
  text ".TID" at 70.955,-21.819 h1.52
  text "PLOT NAME =" at -5.804,-27.034 h1.52
  text ".plot_File_Name" at 14.656,-27.034 h1.52
  text "GENERATED    :" at 57.15,-27.034 h1.52
  text ".Print_Date" at 79.235,-27.034 h1.52
  text ".Print_Time" at 97.752,-27.034 h1.52
  text "TEXAS INSTRUMENTS" at 129.87,-27.034 h1.52
M6 Assembly Bottom:
  lines w0.254: -7.429,-18.474 160.261,-18.474 ; -7.379,-23.639 160.261,-23.639 ; 28.334,-28.969 28.334,-23.817 ; 44.133,-18.474 44.133,-13.31 ; 65.468,-18.474 65.468,-13.31 ; 97.65,-28.804 97.65,-13.31 ; 120.231,-28.804 160.249,-28.804 160.249,-13.31 -7.429,-13.31 -7.429,-28.804 58.534,-28.804 160.261,-28.804 160.261,-13.31
  text "COMPONENTS MARKED 'DNP' SHOULD NOT BE POPULATED." at 154.991,-8.077 h1.52
  text ".VariantName" at 128.473,-11.024 h1.52
  text "ASSEMBLY VARIANT:" at 154.864,-11.024 h1.52
  text ".VersionControl_RevNumber" at 26.302,-16.667 h1.52
  text "SVN REV:" at 39.154,-16.667 h1.52
  text ".PCB_Rev" at 53.035,-16.667 h1.52
  text "REV:" at 60.439,-16.667 h1.52
  text ".PRJ_Number" at 81.89,-16.667 h1.52
  text "BOARD #:" at 95.745,-16.667 h1.52
  text "PCB VIEWED FROM BOTTOM SIDE" at 158.648,-16.667 h1.52
  text ".TID" at 81.89,-21.831 h1.52
  text "TID #:" at 95.745,-21.831 h1.52
  text "TEXAS INSTRUMENTS" at 22.974,-27.047 h1.52
  text ".Print_Time" at 55.093,-27.047 h1.52
  text ".Print_Date" at 73.609,-27.047 h1.52
  text "GENERATED    :" at 95.694,-27.047 h1.52
  text ".plot_File_Name" at 138.189,-27.047 h1.52
  text "PLOT NAME =" at 158.648,-27.047 h1.52
M9 Title Sheet:
  drawing of 57 lines, arcs and shapes, not listed
  text "1" at 18.792,204.127 h1.78
  text "2" at 82.182,204.127 h1.78
  text "3" at 145.411,204.127 h1.78
  text "4" at 209.08,204.127 h1.78
  text "5" at 272.555,204.127 h1.78
  text "6" at 336.182,204.127 h1.78
  text "A" at -10.579,175.095 h1.78
  text "A" at 365.341,175.095 h1.78
  text "B" at -10.579,114.643 h1.78
  text "B" at 365.341,114.643 h1.78
  text "C" at -10.579,54.318 h1.78
  text "C" at 365.341,54.318 h1.78
  text "PROJECT TITLE:" at 288.125,7.048 h1.14
  text ".PRJ_Title" at 289.395,3.662 h1.78
  text "DESIGNED FOR:" at 288.125,-0.597 h1.14
  text ".PRJ_Customer" at 289.395,-4.153 h1.78
  text "D" at -10.579,-5.88 h1.78
  text "D" at 365.341,-5.88 h1.78
  text "FILE NAME:" at 288.125,-8.217 h1.14
  text ".PCB_File_Name_No_Path" at 289.395,-11.265 h1.78
  text "Texas Instruments (TI) and/or its licensors do not warrant the accuracy or completeness of this specification" at 161.9,-15.376 h1.14
  text "ENGINEER:" at 288.125,-15.583 h1.14
  text "LAYOUT BY:" at 326.352,-15.583 h1.14
  text "or any information contained therein. TI and/or its licensors do not warrant that this design will meet" at 160.757,-18.237 h1.14
  text ".PRJ_Engineer" at 289.395,-19.52 h1.78
  text ".PCB_Layout" at 327.635,-19.52 h1.78
  text "the specifications, will be suitable for your application or fit for any particular purpose, or will operate in" at 160.757,-21.099 h1.14
  text ".Layer_Name" at 14.656,-21.806 h1.52
  text "ALTIUM DESIGNER VERSION:" at 326.352,-23.457 h1.14
  text "an implementation. TI and/or its licensors do not warrant that the design is production worthy. You should" at 160.757,-23.961 h1.14
  text "completely validate and test your design implementation to confirm the system functionality for your application." at 161.9,-26.822 h1.14
  text ".print_Scale" at 289.395,-26.843 h1.78
  text ".Application_BuildNumber" at 327.635,-26.843 h1.78
  text "1" at 18.792,-32.093 h1.78
  text "2" at 82.182,-32.093 h1.78
  text "3" at 145.411,-32.093 h1.78
  text "4" at 209.08,-32.093 h1.78
  text "5" at 272.555,-32.093 h1.78
  text "6" at 336.182,-32.093 h1.78
M10 Fab Notes:
  drawing of 189 lines, arcs and shapes, not listed
  text "DESIGN INFORMATION" at 314.503,161.447 h1.52
  text "MIN. TRACK WIDTH:" at 298.131,158.091 h1.52
  text "8" at 325.976,158.091 h1.52
  text "MIL" at 329.907,158.091 h1.52
  text "MIN. CLEARANCE:" at 298.131,154.938 h1.52
  text "0.2" at 324.452,154.938 h1.52
  text "mm" at 329.907,154.938 h1.52
  text "MIN. VIA PAD SIZE:" at 298.131,151.785 h1.52
  text "24" at 325.214,151.785 h1.52
  text "MIL" at 329.907,151.785 h1.52
  text "0.05mm (2MIL)" at 315.784,148.486 h1.52
  text "MINIMUM ANNULAR RING" at 289.769,148.277 h1.52
  text "EXTERNAL" at 333.768,148.277 h1.52
  text "PER" at 294.849,145.48 h1.52
  text "IPC-D-275 CLASS 2 LEVEL C" at 300.437,145.48 h1.52
  text "MIL, HOLES" at 338.238,142.928 h1.52
  text "+/-" at 328.27,142.709 h1.52
  text "+/-" at 349.961,142.709 h1.52
  text "REGISTRATION TOLERANCES:" at 289.769,142.682 h1.52
  text "METAL" at 320.243,142.682 h1.52
  text "5" at 334.879,142.683 h1.52
  text "3" at 356.037,142.683 h1.52
  text "MIL" at 358.99,142.682 h1.52
  text "HOLE SIZE TOLERANCE (UNLESS OTHERWISE SPECIFIED):" at 289.769,140.185 h1.52
  text "+/-" at 349.961,140.112 h1.52
  text "3" at 356.037,140.085 h1.52
  text "MIL" at 358.99,140.085 h1.52
  text "MATERIAL:" at 287.87,136.589 h1.52
  text "FR-4 High Tg" at 312.926,133.324 h1.52
  text "X" at 309.257,133.122 h1.52
  text "FR-408" at 298.563,133.007 h1.52
  text "OTHER" at 336.358,133.007 h1.52
  text "62 MIL (1.6mm) +/-10%" at 306.694,129.374 h1.52
  text "X" at 303.643,129.312 h1.52
  text "THICKNESS:" at 289.769,129.165 h1.52
  text "OTHER" at 339.33,129.165 h1.52
  text "TOLERANCE:" at 289.769,125.652 h1.52
  text "X" at 311.314,125.652 h1.52
  text "ANSI IPC-6012 TYPE 3 CLASS 2" at 315.836,125.652 h1.52
  text "OTHER +/-" at 315.835,121.989 h1.52
  text "BOW & TWIST:" at 289.769,118.302 h1.52
  text "X" at 311.314,118.302 h1.52
  text "ANSI IPC-6012 TYPE 3 CLASS 2" at 315.836,118.302 h1.52
  text "OTHER +/-" at 315.835,114.576 h1.52
  text "DRILLING:" at 287.87,111.258 h1.52
  text "NC_DRILL FILES" at 332.599,108.586 h1.52
  text "REFERENCE:" at 289.769,108.486 h1.52
  text "X" at 306.463,108.484 h1.52
  text "AS SHOWN" at 310.984,108.486 h1.52
  text "X" at 329.348,108.486 h1.52
  text "OTHER" at 340.168,104.873 h1.52
  text "PTH COPPER THICKNESS:" at 289.761,104.783 h1.52
  text "X" at 318.697,104.783 h1.52
  text "20-30 um" at 321.948,104.783 h1.52
  text "BOARD FINISH:" at 287.87,101.034 h1.52
  text "SILKSCREEN:" at 291.812,98.237 h1.52
  text "X" at 316.14,98.237 h1.52
  text "TOP" at 319.112,98.237 h1.52
  text "X" at 329.094,98.237 h1.52
  text "BOTTOM" at 332.091,98.237 h1.52
  text "SILKSCREEN COLOR:" at 291.812,94.295 h1.52
  text "X" at 316.115,94.295 h1.52
  text "WHITE" at 319.112,94.295 h1.52
  text "OTHER" at 332.091,94.295 h1.52
  text "X" at 319.442,90.652 h1.52
  text "GREEN" at 322.439,90.652 h1.52
  text "OTHER" at 338.136,90.652 h1.52
  text "SOLDER RESIST COLOR:" at 291.812,90.477 h1.52
  text "X" at 319.442,86.734 h1.52
  text "MATTE" at 322.439,86.734 h1.52
  text "SEMI-GLOSS" at 338.125,86.717 h1.52
  text "IMMERSION GOLD (ENIG)" at 314.819,82.345 h1.52
  text "ENEPIG" at 348.793,82.162 h1.52
  text "SURFACE FINISH:" at 287.87,82.136 h1.52
  text "X" at 310.298,82.136 h1.52
  text "IMM. TIN/SILVER OR EQUIV" at 296.24,78.649 h1.52
  text "OTHER" at 332.599,78.549 h1.52
  text "ARRAY/PANEL:" at 287.87,74.602 h1.52
  text "CUT AND TRIM PER M1 BOARD OUTLINE" at 314.819,74.393 h1.52
  text "N.C. ROUTE" at 314.819,70.94 h1.52
  text "X" at 332.295,70.94 h1.52
  text "V. SCORE" at 336.816,70.94 h1.52
  text ".Layer_Name" at 48.438,68.304 h1.52
  text "CERTIFICATION:" at 287.87,67.66 h1.52
  text "MATERIALS AND WORKMANSHIP FOR ALL PCBS" at 306.285,67.66 h1.52
  text "TO MEET OR EXCEED THE REQUIREMENTS OF:" at 306.285,65.271 h1.52
  text "X" at 297.078,62.003 h1.52
  text "ANSI IPC-A-600F CLASS ->" at 300.329,62.003 h1.52
  text "X" at 342.188,62.003 h1.52
  text "2" at 344.982,62.003 h1.52
  text "1" at 336.981,61.965 h1.52
  text "3" at 353.973,61.965 h1.52
  text "X" at 317.702,58.252 h1.52
  text "RoHS" at 320.953,58.252 h1.52
  text "OTHER" at 337.321,58.252 h1.52
  text "PER ORDER" at 347.407,58.252 h1.52
  text "ALL BOARDS MUST MEET OR EXCEED UL94-V0 REQUIREMENTS." at 288.569,54.345 h1.52
  text "PCB MUST BEAR THE UL94V-0 UL REGISTERED MATERIAL ID NUMBER" at 288.569,51.397 h1.52
  text "ADDITIONAL REQUIREMENTS:" at 287.87,47.094 h1.52
  text "MICROSECTION:" at 289.769,44.373 h1.52
  text "YES" at 312.775,44.373 h1.52
  text "REQUIRED" at 334.657,40.707 h1.52
  text "BARE BOARD ELEC. TEST:" at 289.769,40.634 h1.52
  text "NONE" at 322.935,40.634 h1.52
  text "X" at 331.66,40.634 h1.52
  text "PER ORDER" at 349.693,40.634 h1.52
  text "XX MIL VIAS REQUIRE NON-CONDUCTIVE FILL AND PLANARIZE" at 294.04,35.428 h1.5
  text "XX MIL VIAS REQUIRE CONDUCTIVE FILL AND PLANARIZE" at 294.243,32.787 h1.52
  text "OUTER XX MIL VIAS REQUIRE 50 OHM SINGLE-ENDED IMPEDANCE" at 294.218,28.637 h1.47
  text "LAYER 2 & 3 (INNER LAYERS) XX MIL WIDE, XX MIL SPACE / TRACES REQUIRE 100 OHM DIFFERENTIAL IMPEDANCE" at 294.015,22.65 h1.52
M11 Gerber Information:
  lines w0.254: -7.417,-23.626 160.223,-23.626 ; -7.417,-18.462 160.274,-18.462 ; -7.417,-13.297 -7.417,-28.791 94.31,-28.791 160.274,-28.791 160.274,-13.297 -7.404,-13.297 -7.404,-28.791 32.614,-28.791 ; 55.194,-28.791 55.194,-13.297 ; 87.376,-18.462 87.376,-13.297 ; 108.712,-18.462 108.712,-13.297 ; 124.511,-28.956 124.511,-23.804
  text "ALL ARTWORK VIEWED FROM TOP SIDE" at -5.804,-16.654 h1.52
  text "BOARD #:" at 57.099,-16.654 h1.52
  text ".PRJ_Number" at 70.955,-16.654 h1.52
  text "REV:" at 92.405,-16.654 h1.52
  text ".PCB_Rev" at 99.809,-16.654 h1.52
  text "SVN REV:" at 113.69,-16.654 h1.52
  text ".VersionControl_RevNumber" at 126.543,-16.654 h1.52
  text "LAYER NAME =" at -5.804,-21.806 h1.52
  text "TID #:" at 57.099,-21.819 h1.52
  text ".TID" at 70.955,-21.819 h1.52
  text "PLOT NAME =" at -5.804,-27.034 h1.52
  text ".plot_File_Name" at 14.656,-27.034 h1.52
  text "GENERATED    :" at 57.15,-27.034 h1.52
  text ".Print_Date" at 79.235,-27.034 h1.52
  text ".Print_Time" at 97.752,-27.034 h1.52
  text "TEXAS INSTRUMENTS" at 129.87,-27.034 h1.52
M12 Stackup:
  drawing of 191 lines, arcs and shapes, not listed
  text "Layer" at 248.675,198.882 h1.52
  text "Name" at 259.086,198.882 h1.52
  text "Material" at 282.702,198.882 h1.52
  text "Thickness" at 304.54,198.882 h1.52
  text "Constant" at 321.046,198.882 h1.52
  text "Board Layer Stack" at 335.52,198.882 h1.52
  text "1" at 248.675,195.834 h1.52
  text "Top Overlay" at 259.086,195.834 h1.52
  text "2" at 248.675,192.786 h1.52
  text "Top Solder" at 259.086,192.786 h1.52
  text "Solder Resist" at 282.702,192.786 h1.52
  text "0.40mil" at 304.54,192.786 h1.52
  text "3.5" at 321.046,192.786 h1.52
  text "3" at 248.675,189.738 h1.52
  text "Top Layer" at 259.086,189.738 h1.52
  text "Copper" at 282.702,189.738 h1.52
  text "1.40mil" at 304.54,189.738 h1.52
  text "4" at 248.675,186.69 h1.52
  text "Dielectric1" at 259.086,186.69 h1.52
  text "FR-4" at 282.702,186.69 h1.52
  text "59.20mil" at 304.54,186.69 h1.52
  text "4.8" at 321.046,186.69 h1.52
  text "5" at 248.675,183.642 h1.52
  text "Bottom Layer" at 259.086,183.642 h1.52
  text "Copper" at 282.702,183.642 h1.52
  text "1.40mil" at 304.54,183.642 h1.52
  text "6" at 248.675,180.594 h1.52
  text "Bottom Solder" at 259.086,180.594 h1.52
  text "Solder Resist" at 282.702,180.594 h1.52
  text "0.40mil" at 304.54,180.594 h1.52
  text "3.5" at 321.046,180.594 h1.52
  text "7" at 248.675,177.546 h1.52
  text "Bottom Overlay" at 259.086,177.546 h1.52
  text ".Layer_Name" at 48.438,71.675 h1.52
M13 Component Bodies Top:
  text ".Layer_Name" at 8.814,56.54 h1.52
M14 Component Bodies Bottom:
  text ".Layer_Name" at 45.314,64.22 h1.52
M15 Courtyards Top:
  text ".Layer_Name" at 8.814,60.173 h1.52
M16 Courtyards Bottom:
  text ".Layer_Name" at 45.314,67.937 h1.52
Drill Drawing:
  circle w0.254: c34.008,70.213 r0.562
  lines w0.254: 33.446,72.462 33.727,72.462 34.008,72.181 34.289,72.462 34.57,72.462 34.289,72.743 34.57,73.025 34.289,73.025 34.008,73.306 33.727,73.025 33.446,73.025 33.727,72.743 33.446,72.462 ; 33.446,74.711 34.57,74.711 34.57,75.836 33.446,75.836 33.446,74.711 ; 33.446,77.242 34.008,77.523 34.57,77.242 34.289,77.804 34.57,78.367 34.008,78.085 33.446,78.367 33.727,77.804 33.446,77.242 ; 33.446,80.897 34.57,80.897 34.008,79.772 33.446,80.897
  lines w0.305: 32.41,68.892 111.479,68.892 ; 32.41,81.544 111.479,81.544 ; 40.428,66.361 40.428,84.074 ; 48.484,66.361 48.484,84.074 ; 64.276,66.361 64.276,84.074 ; 70.482,66.361 70.482,84.074 ; 79.635,66.361 79.635,84.074 ; 97.656,66.361 97.656,84.074 ; 32.41,66.361 111.479,66.361 111.479,84.074 32.41,84.074 32.41,66.361
  text "Symbol" at 33.929,82.303 h1.83
  text "Quantity" at 41.187,82.303 h1.83
  text "Finished Hole Size" at 49.243,82.303 h1.83
  text "Plated" at 65.035,82.303 h1.83
  text "Hole Type" at 71.241,82.303 h1.83
  text "Drill Layer Pair" at 80.394,82.303 h1.83
  text "Hole Tolerance" at 98.415,82.303 h1.83
  text "53" at 41.187,79.772 h1.52
  text "7.87mil (0.200mm)" at 49.243,79.772 h1.52
  text "PTH" at 65.035,79.772 h1.52
  text "Round" at 71.241,79.772 h1.52
  text "Top Layer - Bottom Layer" at 80.394,79.772 h1.52
  text "386" at 41.187,77.242 h1.52
  text "11.81mil (0.300mm)" at 49.243,77.242 h1.52
  text "PTH" at 65.035,77.242 h1.52
  text "Round" at 71.241,77.242 h1.52
  text "Top Layer - Bottom Layer" at 80.394,77.242 h1.52
  text "2" at 41.187,74.711 h1.52
  text "43.31mil (1.100mm)" at 49.243,74.711 h1.52
  text "PTH" at 65.035,74.711 h1.52
  text "Round" at 71.241,74.711 h1.52
  text "Top Layer - Bottom Layer" at 80.394,74.711 h1.52
  text "40" at 41.187,72.181 h1.52
  text "45.28mil (1.150mm)" at 49.243,72.181 h1.52
  text "PTH" at 65.035,72.181 h1.52
  text "Round" at 71.241,72.181 h1.52
  text "Top Layer - Bottom Layer" at 80.394,72.181 h1.52
  text "4" at 41.187,69.651 h1.52
  text "125.98mil (3.200mm)" at 49.243,69.651 h1.52
  text "PTH" at 65.035,69.651 h1.52
  text "Round" at 71.241,69.651 h1.52
  text "Top Layer - Bottom Layer" at 80.394,69.651 h1.52
  text "485 Total" at 41.187,67.12 h1.52
  text ".Layer_Name" at 14.656,-21.806 h1.52
M17 Embedded Cavity:
  text ".Layer_Name" at 48.438,58.191 h1.52
M18 Embedded Assembly:
  text ".Layer_Name" at 48.438,61.562 h1.52
M19 Embedded Keepout:
  text ".Layer_Name" at 48.438,64.933 h1.52
Mechanical 24:
  drawing of 673 lines, arcs and shapes, not listed

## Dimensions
0,0 to 177.8,1.778 on M2 Board Dimensions
0,0 to 1.778,50.8 on M2 Board Dimensions
0,-10.16 to 25.4,-10.16 on M2 Board Dimensions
